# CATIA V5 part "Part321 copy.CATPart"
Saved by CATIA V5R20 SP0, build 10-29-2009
Part number: Main Part
Material "Aluminium Grey": density 7860 kg/m3, Young's modulus 2e+11 Pa, Poisson ratio 0.266
Bounding box of the stored display mesh (mm): x -38.482 to 38, y -61.662 to 61.662, z -10.315 to 15.099
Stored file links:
  C:\Users\scupi\Desktop\Product\Part321 copy.CATPart
  C:\Program Files\Dassault Systemes\B20\win_b64\startup\materials\Catalog.CATMaterial
  C:\Users\scupi\Desktop\Projrct\Projrct\Product1.CATProduct
  C:\Users\scupi\Desktop\Projrct\Projrct\Part1.CATPart
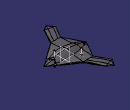
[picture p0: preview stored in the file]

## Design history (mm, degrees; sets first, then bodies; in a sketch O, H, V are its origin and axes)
Body1 (main body), material "Aluminium Grey"
  Sketch1 on xy-plane, origin (0, 0, 0), H (1, 0, 0), V (0, 1, 0)
    point P1 (38.3413, 0)
    line L1 (38.3413, 0) -> (-3.7062, -29.4535)
    point P2 (-3.7062, -29.4535)
    line L2 (-3.7062, -29.4535) -> (-18.4071, -55.3903)
    point P3 (-18.4071, -55.3903)
    line L3 (-18.4071, -55.3903) -> (-27.3607, -61.6621)
    point P4 (-27.3607, -61.6621)
    line L4 (-27.3607, -61.6621) -> (-34.7097, -51.1708)
    point P5 (-34.7097, -51.1708)
    line L5 (-34.7097, -51.1708) -> (-21.2524, -29.4535)
    point P6 (-21.2524, -29.4535)
    line L6 (-21.2524, -29.4535) -> (-38.4824, 0)
    point P7 (-38.4824, 0)
    point P8 (-3.7062, 29.4535)
    point P9 (38.3413, 0)
    line L7 (38.3413, 0) -> (-3.7062, 29.4535)
    point P10 (-18.4071, 55.3903)
    line L8 (-3.7062, 29.4535) -> (-18.4071, 55.3903)
    point P11 (-27.3607, 61.6621)
    line L9 (-18.4071, 55.3903) -> (-27.3607, 61.6621)
    point P12 (-34.7097, 51.1708)
    line L10 (-27.3607, 61.6621) -> (-34.7097, 51.1708)
    point P13 (-21.2524, 29.4535)
    line L11 (-34.7097, 51.1708) -> (-21.2524, 29.4535)
    point P14 (-38.4824, 0)
    line L12 (-21.2524, 29.4535) -> (-38.4824, 0)
    point P15 (0, 26.8574)
    construction line L13 (-3.7062, 29.4535) -> (-3.7062, -29.4535)
    point P16 (-18.4071, 55.3903)
    construction line L14 (-3.7062, 29.4535) -> (-21.2524, 29.4535)
    construction line L15 (-3.7062, -29.4535) -> (-21.2524, -29.4535)
    construction line L16 (-18.4071, 55.3903) -> (-18.4071, -55.3903)
    point P17 (-18.4071, 29.4535)
    point P18 (-18.4071, -29.4535)
    coincidence: P1 H, P5 L1, P7 H, P1 P9, P7 P14, P15 L7, P15 V, P16 P10, P17 L14, P17 L16, P18 L15, P18 L16
    parallelism: L3 L1
    perpendicularity: L4 L1
    symmetry: P2 P8 H, P1 P9 H, L1 L7 H, P3 P10 H, L2 L8 H, P4 P11 H, L3 L9 H, P5 P12 H, L4 L10 H, P6 P13 H, L5 L11 H, P7 P14 H, L6 L12 H
    fix: L2, L1, L7, L8, L9, L10, L11, L12, L6, L5, L4, L3
    vertical: L13 V, L16 V
    horizontal: L14 H, L15 H
  Sketch2 on zx-plane, origin (0, 0, 0), H (-1, 0, 0), V (0, 0, 1)
    spline S1 through (-38.342, 0.0001) (-29.0478, 2.6828) (-23.5392, 3.3948) (-18.2571, 5.3987) (-13.4407, 6.9001) (-6.5094, 7.7091) (10.4145, 6.38) (23.4684, 4.5885) (33.5188, 2.0458) (38.4824, 0)
    spline S2 through (-38.342, 0.0001) (-23.6998, -2.2041) (-10.8836, -3.4422) (0, -3.9728) (25.7975, -2.2042) (38.4824, 0)
    reference projected point E1 (-38.3413, 0) from vertex [element of Sketch1 | element of Sketch1]
    reference projected point E2 (38.4824, 0) from vertex [element of Sketch1 | element of Sketch1]
    point P2 (38.4824, 0)
    point P3 (-38.342, 0.0001)
    point P4 (0, -3.9728)
    point P5 (38.4824, 0)
    point P6 (-38.342, 0.0001)
    coincidence: P2 H, P4 V, P5 P2, P6 P3, S2 E1, P5 E2
  Plane1: type OffsetPt, RefPlane yz-plane, RefPoint vertex [element of Sketch1 | element of Sketch1]
  Sketch3 "guide" on Plane1, origin (-3.7062, 0, 0), H (0, 1, 0), V (0, 0, 1)
    point P1 (29.4535, -0.9235)
    spline S1 through (29.4535, -0.9235) (0, -4.6081) (-29.4535, -0.9235)
    point P2 (-29.4535, -0.9235)
    point P3 (8.7411, 2.2116)
    spline S2 through (8.7411, 2.2116) (0, 5.1926) (-8.7411, 2.2116)
    point P4 (-8.7411, 2.2116)
    line L1 (-29.4535, 1.1371) -> (-29.4535, -0.9235)
    point P5 (-29.4535, 1.1371)
    point P6 (-29.4535, -0.9235)
    reference projected point E1 (-29.4535, 0) from vertex [element of Sketch1 | element of Sketch1]
    line L2 (-29.4535, 1.1371) -> (-8.7411, 2.2116)
    point P7 (-8.7411, 2.2116)
    point P8 (29.4535, -0.9235)
    point P9 (8.7411, 2.2116)
    point P10 (29.4535, 1.1371)
    line L3 (29.4535, 1.1371) -> (8.7411, 2.2116)
    line L4 (29.4535, 1.1371) -> (29.4535, -0.9235)
    point P11 (29.4535, -0.9235)
    point P12 (0, -4.6081)
    point P13 (-29.4535, -0.9235)
    point P14 (8.7411, 2.2116)
    point P15 (0, 5.1926)
    point P16 (-8.7411, 2.2116)
    coincidence: P11 P1, P12 V, P2 P13, P14 P3, P15 V, P4 P16, L1 E1, P16 P7, P13 P6
    symmetry: P1 P2 V, P3 P4 V, P6 P8 V, P7 P9 V, P5 P10 V, L2 L3 V, L1 L4 V
    vertical: L1 V
  Plane2: type OffsetPt, RefPlane Plane1, RefPoint vertex [element of Sketch1 | element of Sketch1]
  Intersect1: ToIntersect1 Plane2, ToIntersect2 Sketch2
  Sketch4 "sec3" on Plane2, origin (-21.2524, 0, 0), H (0, 1, 0), V (0, 0, 1)
    point P1 (-8.0407, 2.5464)
    point P2 (8.0407, 2.5464)
    spline S1 through (-8.0407, 2.5464) (0, 4.9535) (8.0407, 2.5464)
    reference projected point E1 (0, 4.9535) from vertex of Intersect1
    line L1 (-29.4535, 1.3652) -> (-29.4535, -0.4022)
    point P3 (-29.4535, 1.3652)
    point P4 (-29.4535, -0.4022)
    reference projected point E2 (-29.4535, 0) from vertex [element of Sketch1 | element of Sketch1]
    line L2 (-29.4535, 1.3652) -> (-8.0407, 2.5464)
    point P5 (8.0407, 2.5464)
    point P6 (29.4535, 1.3652)
    line L3 (29.4535, 1.3652) -> (8.0407, 2.5464)
    point P7 (29.4535, -0.4022)
    line L4 (29.4535, 1.3652) -> (29.4535, -0.4022)
    spline S2 through (29.4535, -0.4022) (0, -2.8109) (-29.4535, -0.4022)
    reference projected point E3 (0, -2.8109) from vertex of Intersect1
    point P8 (-8.0407, 2.5464)
    point P9 (0, 4.9535)
    point P10 (8.0407, 2.5464)
    point P11 (29.4535, -0.4022)
    point P12 (0, -2.8109)
    point P13 (-29.4535, -0.4022)
    symmetry: P1 P2 V, P1 P5 V, P3 P6 V, L2 L3 V, P4 P7 V, L1 L4 V
    coincidence: P8 P1, P9 V, P10 P2, P9 E1, L1 E2, P11 P7, P12 V, P13 P4, P12 E3
    vertical: L1 V
  Intersect2: ToIntersect1 Plane1, ToIntersect2 Sketch2
  Sketch5 "sec2" on Plane1, origin (-3.7062, 0, 0), H (0, 1, 0), V (0, 0, 1)
    point P1 (-29.4535, 1.4416)
    line L1 (-11.0148, 3.0889) -> (-29.4535, 1.4416)
    point P2 (-11.0148, 3.0889)
    line L2 (-29.4535, 1.4416) -> (-29.4535, -0.6915)
    point P3 (-29.4535, -0.6915)
    point P4 (29.4535, 1.4416)
    point P5 (11.0148, 3.0889)
    line L3 (11.0148, 3.0889) -> (29.4535, 1.4416)
    point P6 (29.4535, -0.6915)
    point P7 (29.4535, 1.4416)
    line L4 (29.4535, 1.4416) -> (29.4535, -0.6915)
    spline S1 through (29.4535, -0.6915) (0, -3.993) (-29.4535, -0.6915)
    reference projected point E1 (0, -3.993) from vertex of Intersect2
    reference projected point E2 (-29.4535, 0) from vertex [element of Sketch1 | element of Sketch1]
    spline S2 through (11.0148, 3.0889) (0, 7.1824) (-11.0148, 3.0889)
    reference projected point E3 (0, 7.1824) from vertex of Intersect2
    point P8 (29.4535, -0.6915)
    point P9 (0, -3.993)
    point P10 (-29.4535, -0.6915)
    point P11 (11.0148, 3.0889)
    point P12 (0, 7.1824)
    point P13 (-11.0148, 3.0889)
    vertical: L2 V
    symmetry: P1 P4 V, P2 P5 V, L1 L3 V, P3 P6 V, P1 P7 V, L2 L4 V
    coincidence: P8 P6, P9 V, P10 P3, P9 E1, L2 E2, P11 P5, P12 V, P13 P2, P12 E3
    fix: L2, L4
  Sketch6 on zx-plane, origin (0, 0, 0), H (-1, 0, 0), V (0, 0, 1)
    projected curve E1 from Sketch2.S1
  Sketch7 on zx-plane, origin (0, 0, 0), H (-1, 0, 0), V (0, 0, 1)
    projected curve E1 from Sketch2.S2
  Line1: type PtPt, FirstPoint vertex [element of Sketch1 | element of Sketch1], SecondPoint vertex [element of Sketch1 | element of Sketch1]
  Line2: type PtPt, FirstPoint vertex [element of Sketch1 | element of Sketch1], SecondPoint vertex [element of Sketch1 | element of Sketch1]
  Join1: Elements (Sketch1.L1; Line1; Sketch1.L6)
  Join2: Elements (Sketch1.L7; Line2; Sketch1.L12)
  Point1: type OnCurve, Support Sketch6, Length 63.448
  Plane3: type OffsetPt, RefPlane yz-plane, RefPoint Point1
  Intersect3: ToIntersect1 Plane3, ToIntersect2 Sketch7
  Intersect4: ToIntersect1 Plane3, ToIntersect2 Join1
  Sketch8 "sec1" on Plane3, origin (23.3769, 0, 0), H (0, 1, 0), V (0, 0, 1)
    point P1 (6.8279, 0.7116)
    point P2 (-6.8279, 0.7116)
    spline S1 through (6.8279, 0.7116) (0, 3.4379) (-6.8279, 0.7116)
    point P3 (10.5778, 0)
    point P4 (-10.4823, 0)
    reference projected point E1 (0, 3.4379) from Point1
    reference projected line E2 (0, 0) -> (29.4535, 0) from Sketch1.L7
    reference projected point E3 (-10.4823, 0) from Intersect4
    line L1 (-10.4823, 0.2663) -> (-10.4823, -0.3361)
    point P5 (-10.4823, 0.2663)
    point P6 (-10.4823, -0.3361)
    reference projected point E4 (-10.4823, 0) from Intersect4
    line L2 (-10.4823, 0.2663) -> (-6.8279, 0.7116)
    point P7 (6.8279, 0.7116)
    point P8 (10.4823, 0.2663)
    line L3 (10.4823, 0.2663) -> (6.8279, 0.7116)
    point P9 (10.4823, -0.3361)
    line L4 (10.4823, 0.2663) -> (10.4823, -0.3361)
    spline S2 through (-10.4823, -0.3361) (0, -2.2426) (10.4823, -0.3361)
    reference projected point E5 (0, -2.2426) from Intersect3
    point P10 (6.8279, 0.7116)
    point P11 (0, 3.4379)
    point P12 (-6.8279, 0.7116)
    point P13 (-10.4823, -0.3361)
    point P14 (0, -2.2426)
    point P15 (10.4823, -0.3361)
    symmetry: P1 P2 V, P2 P7 V, P5 P8 V, L2 L3 V, P6 P9 V, L1 L4 V
    coincidence: P10 P1, P11 V, P12 P2, P11 E1, P3 E2, P4 E3, L1 E4, P13 P6, P14 V, P15 P9, P14 E5
    vertical: L1 V
    fix: L1, L4
  LineCorner1: Elements (vertex [element of Sketch1 | element of Sketch1]; vertex [element of Sketch4 | element of Sketch4]; vertex [element of Sketch5 | element of Sketch5]; vertex [element of Sketch8 | element of Sketch8]; vertex [element of Sketch1 | element of Sketch1])
  LineCorner2: Elements (vertex [element of Sketch1 | element of Sketch1]; vertex [element of Sketch4 | element of Sketch4]; vertex [element of Sketch5 | element of Sketch5]; vertex [element of Sketch8 | element of Sketch8]; vertex [element of Sketch1 | element of Sketch1])
  LineCorner3: Elements (vertex [element of Sketch1 | element of Sketch1]; vertex [element of Sketch4 | element of Sketch4]; vertex [element of Sketch5 | element of Sketch5]; vertex [element of Sketch8 | element of Sketch8]; vertex [element of Sketch1 | element of Sketch1])
  LineCorner4: Elements (vertex [element of Sketch1 | element of Sketch1]; vertex [element of Sketch4 | element of Sketch4]; vertex [element of Sketch5 | element of Sketch5]; vertex [element of Sketch8 | element of Sketch8]; vertex [element of Sketch1 | element of Sketch1])
  Curve1: Elements (vertex [element of Sketch1 | element of Sketch1]; vertex [element of Sketch4 | element of Sketch4]; vertex [element of Sketch5 | element of Sketch5]; vertex [element of Sketch8 | element of Sketch8]; vertex [element of Sketch1 | element of Sketch1])
  Curve2: Elements (vertex [element of Sketch1 | element of Sketch1]; vertex [element of Sketch4 | element of Sketch4]; vertex [element of Sketch5 | element of Sketch5]; vertex [element of Sketch8 | element of Sketch8]; vertex [element of Sketch1 | element of Sketch1])
  Plane4: type Offset, RefPlane yz-plane, Offset 38
  Intersect5: ToIntersect1 Plane4, ToIntersect2 Sketch2
  Extremum1: Reference Sketch2, Direction (1, 2, 3)
  Intersect6: ToIntersect1 Plane4, ToIntersect2 Curve2
  Intersect7: ToIntersect1 Plane4, ToIntersect2 Curve1
  Curve3: Elements (vertex of Intersect5; Intersect6; vertex of Intersect5; Intersect7; vertex of Intersect5)
  Loft1: Sections (Curve3; Sketch8), Guides (Sketch6; Curve2; Sketch7; Curve1)
  Loft2: Sections (Sketch8; Sketch5; Sketch4), Guides (Sketch6; Curve2; Sketch7; Curve1; LineCorner2; LineCorner3; LineCorner1; LineCorner4)
  Fill1: Boundary (edge of Loft1; edge of Loft1; edge of Loft1; edge of Loft1)
  Join3: Elements (Loft1; Loft2; Fill1)
  CloseSurface1: CloseElement Join3
  Plane5: type Offset, RefPlane face of CloseSurface1, Offset 0, reversed
  Sketch9 on Plane5, origin (0, 29.4535, 0), H (1, 0, 0), V (0, 0, 1)
  Line3: type PtPt, FirstPoint vertex [element of Sketch1 | element of Sketch1], SecondPoint vertex [element of Sketch1 | element of Sketch1]
  Point2: (0, 0, 1), relative to vertex [element of Sketch1 | element of Sketch1]
  Plane6: type 3Points, Element1 Point2, Element2 vertex [element of Sketch1 | element of Sketch1], Element3 vertex [element of Sketch1 | element of Sketch1]
  Sketch10 on Plane6, origin (-14.5919, 56.3778, 0), H (0.9681, 0.2506, 0), V (0, 0, 1)
    point P1 (-3.9409, 0.3267)
    line L1 (-20.7807, 0.4) -> (-20.7807, -0.155)
    line L2 (-3.9409, -0.155) -> (-3.9409, 0.3267)
    point P2 (-20.7807, 0.4)
    point P3 (-20.7807, -0.155)
    point P4 (-3.9409, -0.155)
    reference projected point E1 (-20.7807, 0) from vertex [element of Sketch1 | element of Sketch1]
    reference projected point E2 (-3.9409, 0) from vertex [element of Sketch1 | element of Sketch1]
    line L3 (-3.9409, 0.3267) -> (-3.9409, 0.3267)
    line L4 (-9.2642, 0.9) -> (-16.9401, 0.9)
    arc A1 centre (-9.2642, -24.1) radius 25 from (-3.9409, 0.3267) to (-9.2642, 0.9) ccw
    point P5 (-3.9409, 0.3267)
    reference projected line E3 (-20.7807, 0) -> (-3.9409, 0) from Line3
    line L5 (-20.7807, 0.4) -> (-20.7807, 0.4)
    arc A2 centre (-16.9401, -14.1) radius 15 from (-20.7807, 0.4) to (-16.9401, 0.9) cw
    point P8 (-20.7807, 0.4)
    line L6 (-3.9409, -0.155) -> (-3.9409, -0.155)
    line L7 (-9.8048, -0.5) -> (-16.244, -0.5)
    line L8 (-20.7807, -0.155) -> (-20.7807, -0.155)
    arc A3 centre (-9.8048, 49.5) radius 50 from (-3.9409, -0.155) to (-9.8048, -0.5) cw
    point P11 (-3.9409, -0.155)
    reference projected line E4 (-20.7807, 0) -> (-3.9409, 0) from Line3
    arc A4 centre (-16.244, 29.5) radius 30 from (-16.244, -0.5) to (-20.7807, -0.155) cw
    point P15 (-20.7807, -0.155)
    radius A1 = 25
    distance L4 E3 = 0.9
    radius A2 = 15
    distance L7 H = 0.5
    radius A3 = 50
    distance P1 E4 = 0.3267
    distance P4 H = 0.155
    radius A4 = 30
    distance P2 H = 0.4
    distance P3 H = 0.155
    vertical: L1 V, L2 V
    coincidence: L1 E1, L2 E2, P5 P1, P8 P2, P11 P4, P15 P3
    horizontal: L4 H, L7 H
    tangency: A1 L3, A1 L4, A2 L5, A2 L4, A3 L6, A3 L7, A4 L7, A4 L8
  LineCorner5: Elements (vertex [element of Sketch5 | element of Sketch5]; vertex [element of Sketch10 | element of Sketch10]; vertex [element of Sketch1 | element of Sketch1])
  LineCorner6: Elements (vertex [element of Sketch5 | element of Sketch5]; vertex [element of Sketch10 | element of Sketch10]; vertex of LineCorner5)
  LineCorner7: Elements (vertex [element of Sketch4 | element of Sketch4]; vertex [element of Sketch10 | element of Sketch10]; vertex of LineCorner5)
  LineCorner8: Elements (vertex [element of Sketch4 | element of Sketch4]; vertex [element of Sketch10 | element of Sketch10]; vertex of LineCorner5)
  Loft3: Sections (Sketch9; Sketch10), Guides (LineCorner5; LineCorner6; LineCorner7; LineCorner8)
  Symmetry1: ToTransfor Loft3, Reference zx-plane
  CloseSurface2: CloseElement Loft3
  CloseSurface3: CloseElement Symmetry1
  Plane7: type OffsetPt, RefPlane yz-plane, RefPoint vertex [element of Sketch1 | element of Sketch1]
  Body2
    Plane8: type OffsetPt, RefPlane yz-plane, RefPoint vertex [face of CloseSurface3 | face of CloseSurface3 | face of CloseSurface3 | face of CloseSurface3]
    Point3: type OnCurve, Support edge [face of CloseSurface3 | face of CloseSurface3], Ratio 0.75
    Plane9: type OffsetPt, RefPlane Plane8, RefPoint Point3
    Intersect8: ToIntersect1 Plane9, ToIntersect2 Join3
    Sketch11 on Plane9, origin (-31.3453, 0, 0), H (0, 1, 0), V (0, 0, 1)
      offset curve E1 from edge of Intersect8
      offset curve E2 from edge of Intersect8
      point P1 (0, 2.4052)
      point P2 (-3.8494, 1.0123)
      point P3 (-3.593, 1.1836)
      line L1 (-3.593, 1.1836) -> (-3.593, 0)
      point P4 (-3.593, 0)
      line L2 (-3.593, 0) -> (-0.35, 0)
      point P5 (-0.35, 0)
      line L3 (-0.35, 0) -> (-0.35, 2.3926)
      point P6 (-0.35, 2.3926)
      point P7 (0.35, 2.3926)
      point P8 (0.35, 0)
      line L4 (0.35, 0) -> (0.35, 2.3926)
      point P9 (3.8494, 1.0123)
      point P10 (0, 2.4052)
      point P11 (3.593, 1.1836)
      point P12 (3.593, 0)
      line L5 (3.593, 0) -> (0.35, 0)
      construction frozenspline C1
      frozenspline C2
      line L6 (3.593, 0) -> (3.593, 1.1836)
      distance L3 V = 0.35
      coincidence: P3 E1, P6 E1, L2 H
      horizontal: L2 H
      vertical: L3 V, L1 V, L6 V
      symmetry: P6 P7 V, P5 P8 V, L3 L4 V, P2 P9 V, P1 P10 V, P3 P11 V, P4 P12 V, L2 L5 V
    Pad1: profile Sketch11, direction (-1, 0, 0), length 15
  Remove1: tool Body2
  Fillet1: radius 0.5, on edge [face of Pad1 from Sketch11.L5 | face of Pad1 from Sketch11.L4]; edge [face of Pad1 from Sketch11.L3 | face of Pad1 from Sketch11.L2]
  Point4: (0, 10, 0), relative to Point1
  Line4: type PtPt, FirstPoint Point4, SecondPoint Point1
  Plane10: type Angle, RefPlane Plane7, Direction Line4, Angle -60
  Point5: (0, 0, 0), relative to vertex [face of CloseSurface1 | face of CloseSurface1 | face of CloseSurface1]
  Point6: (0, 0, 0), relative to vertex [face of CloseSurface1 | face of CloseSurface1 | face of CloseSurface1]
  Line5: type PtPt, FirstPoint Point6, SecondPoint Point5
  Point7: (0, 0, 0), relative to vertex [element of Sketch8 | element of Sketch8]
  Point8: (0, 0, 0), relative to vertex [element of Sketch8 | element of Sketch8]
  Line6: type PtPt, FirstPoint Point7, SecondPoint Point8
  Sketch12 on zx-plane, origin (0, 0, 0), H (-1, 0, 0), V (0, 0, 1)
    projected curve E1 from edge [face of CloseSurface1 | face of CloseSurface1]
    projected line E2 (-23.3769, 0.7116) -> (-23.3769, 3.4379) from Sketch8.S1
    projected line E3 (-38, -0.0004) -> (-38, 0.2046) from edge [face of CloseSurface1 | face of CloseSurface1]
    projected curve E4 from edge [face of CloseSurface1 | face of CloseSurface1]
  Pocket1: profile Sketch12, direction (0, -1, 0), length 8, mirrored extent
  Sketch13 on zx-plane, origin (0, 0, 0), H (-1, 0, 0), V (0, 0, 1)
    reference projected curve E1 from edge [face of CloseSurface1 | face of CloseSurface1]
    point P3 (-18.5977, 1.1795)
    coincidence: P3 E1
  Plane11: type 3Points, Element1 Sketch13, Element2 Point7, Element3 Point8
  Sketch14 on Plane11, origin (0.2948, 0, 2.9716), H (0, -1, 0), V (-0.9952, 0, 0.0974)
    line L1 (-6.8279, -23.1924) -> (0, -18.3904)
    line L2 (0, -18.3904) -> (6.8279, -23.1924)
    line L3 (6.8279, -23.1924) -> (-6.8279, -23.1924)
    horizontal: L3 H
  Pocket2: profile Sketch14, direction (0.0974, 0, 0.9952), length 8
  Body3
    Line7: type PtPt, FirstPoint Sketch13, SecondPoint Point8
    Line8: type PtPt, FirstPoint Sketch13, SecondPoint Point7
    Line9: type Normal, RefPoint Sketch13, RefSkin Plane11, Start 0, End 10
    Point9: (0, 0, 0), relative to vertex of Line9
    Line10: type Normal, RefPoint Sketch13, RefSkin zx-plane, Start 0, End 10
    Point10: (0, 0, 0), relative to vertex of Line10
    Plane12: type 3Points, Element1 Point10, Element2 Sketch13, Element3 Point9
    Plane13: type OffsetPt, RefPlane Plane12, RefPoint Point7
    Sketch15 on Plane13, origin (23.0859, 0, -2.2604), H (0, -1, 0), V (0.0974, 0, 0.9952)
      projected curve E1 from edge [face of Pocket2 from Sketch14.L1 | face of CloseSurface1]
      projected line E2 (0, 2.9862) -> (-6.8279, 2.9862) from Line8
      projected line E3 (0, 2.9862) -> (6.8279, 2.9862) from Line7
      projected curve E4 from edge [face of CloseSurface1 | face of Pocket2 from Sketch14.L2]
    Pad2: profile Sketch15, direction (-0.9952, 0, 0.0974), length 8
  Remove2: tool Body3
  Body4
    Plane14: type 3Points, Element1 Point7, Element2 Point8, Element3 Point5
    Sketch16 on zx-plane, origin (0, 0, 0), H (-1, 0, 0), V (0, 0, 1)
      projected point E1 (-18.5977, 1.1795) from Sketch13.P3
      projected point E2 (-38, -0.0004) from Point6
      spline S1 through (-18.5977, 1.1795) (-24.4167, 2.0209) (-28.2156, 1.3263) (-33.3579, 0.5476) (-36.2963, 0.3161) (-38, -0.0004)
      point P1 (-18.5977, 1.1795)
      point P2 (-38, -0.0004)
      coincidence: P1 E1, P2 E2
    Line11: type PtPt, FirstPoint Sketch16.P2, SecondPoint Point6
    Line12: type PtPt, FirstPoint Sketch16.P2, SecondPoint Point5
    Fill2: Boundary (Sketch16; Line8; edge [face of Pocket1 from Sketch12.E1 | face of CloseSurface1]; Line11)
    Fill3: Boundary (Line7; edge [face of CloseSurface1 | face of Pocket1 from Sketch12.E1]; Line12; Sketch16)
    Fill4: Boundary (edge of Fill3; Line7; Line8; edge of Fill2; Line11; Line12)
    Join4: Elements (Fill4; Fill2; Fill3)
    CloseSurface4: CloseElement Join4
  Add1: tool Body4
  Fillet2: on edge [face of CloseSurface3 | face of CloseSurface3] (x2)
  Fillet3: on edge [face of CloseSurface1 | face of CloseSurface1] (x2)
  Fillet4: on edge [face of CloseSurface2 | face of CloseSurface2] (x2)
  Fillet5: on edge [face of CloseSurface1 | face of CloseSurface1] (x2)
  Line13: type PtDir, RefPoint vertex [face of Pad2 from Sketch15.E4 | face of Pad2 from Sketch15.E1 | face of CloseSurface1 | face of CloseSurface1], Direction xy-plane, Start 0, End 10
  Point11: type OnSurface, Support face of CloseSurface1, Length 1.869, Direction (-0.0385, -0.9956, 0.0856)
  Line14: type PtDir, RefPoint Point11, Direction xy-plane, Start 0, End 10
  Body5
    Solid1: solid without history
  Add2: tool Body5
  Body6
    Solid2: solid without history
  Add3: tool Body6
